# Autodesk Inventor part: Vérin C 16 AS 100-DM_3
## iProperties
Shininess: 20.0
Angle Display Precision: 2
Document Length Units: 11269
Document Angle Units: 11279
Document Time Units: 11290
Document Mass Units: 11283
Document Length Units Precision: 3
Document Angle Units Precision: 2
Created: 2002-02
Part Number: Vérin C 16 AS 100-DM_3
Material: Par défaut
Document SubType Name: Modélisation
Designer: Administrateur
Density: 0.0
Volumn: 0.0
Area: 0.0
PropertySet Name: Model Information
Control State: 0
Master: False
Checked Out: False
Author: Administrateur
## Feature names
1. Base1
